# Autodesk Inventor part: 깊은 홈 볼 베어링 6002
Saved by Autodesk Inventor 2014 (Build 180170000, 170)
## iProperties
Created: 2025-10
Part Number: 깊은 홈 볼 베어링 6002
Material: 일반
Document SubType Name: Modeling
Designer: dg
Density: 1 g/cm^3
Appearance: 기본값
Author: dg
Author: jhkim
Description: 깊은 그루브 볼 베어링
Creation Date: 2025-10-01
Sending System: Autodesk Inventor 2026
Preprocessor: ST-DEVELOPER v20.1
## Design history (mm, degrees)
node "깊은 홈 볼 베어링 60021"
body "Solid1"
node "Solid1_1"
node "Solid1_2"
node "Solid1_3"
node "Solid1_4"
node "Solid1_5"
node "Solid1_6"
node "Solid1_7"
node "Solid1_8"
node "Solid1_9"
node "기준1"
node "기준2"
node "기준3"
node "기준4"
node "기준5"
node "기준6"
node "기준7"
node "기준8"
node "기준9"
node "기준10"
